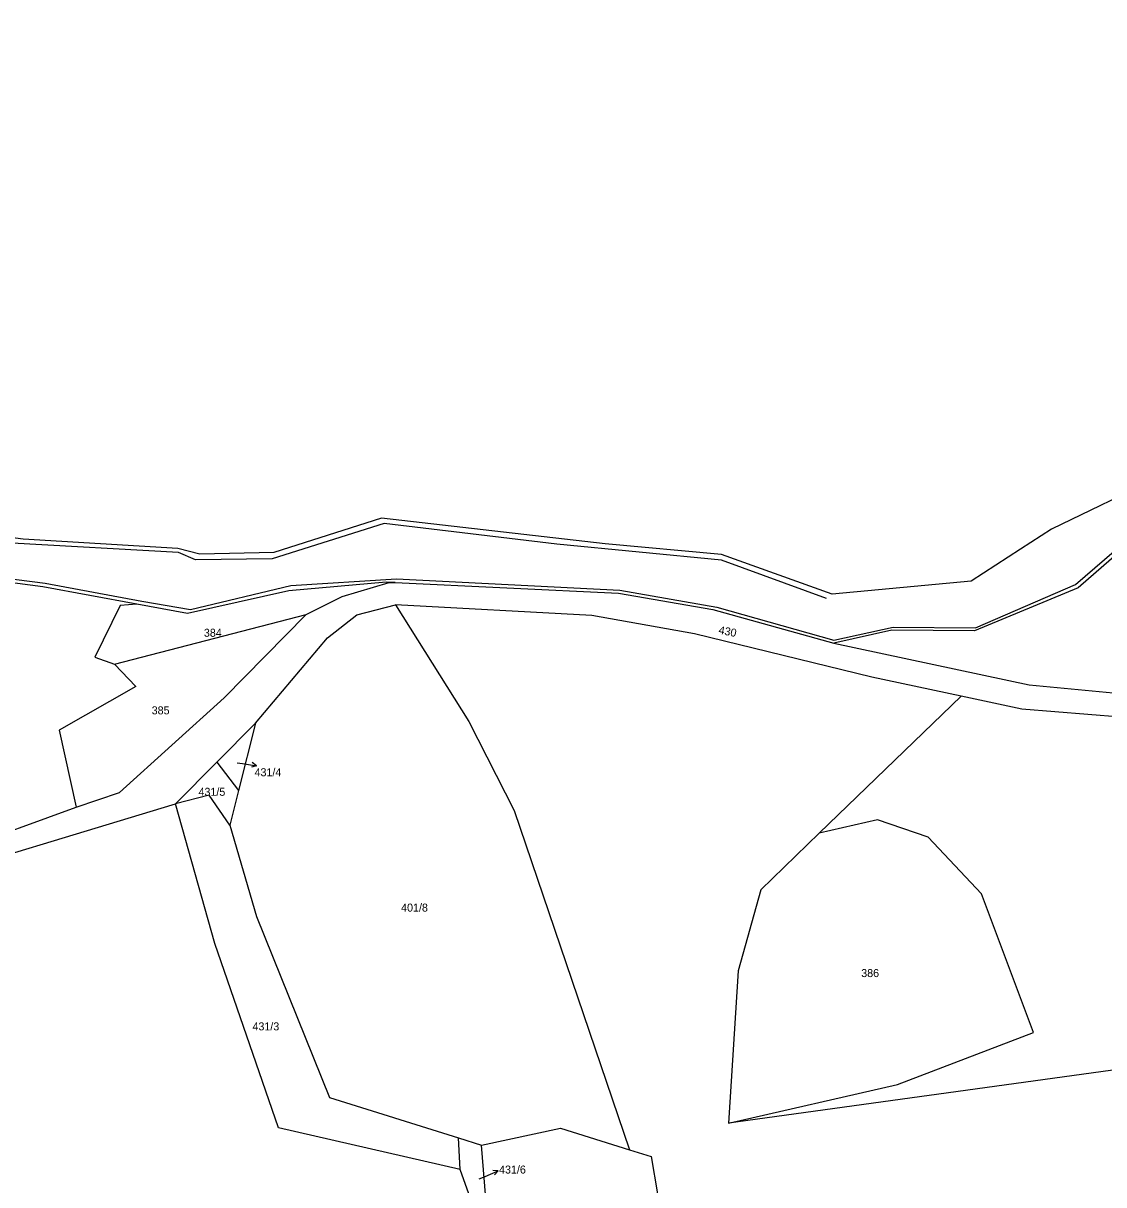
# Model space of a CAD drawing. Extents: x -880531 to -877616, y -1023932 to -1021350.
# Drawn here: x -879514.7 to -879285.2, y -1022591 to -1022344.3 of the extents above; entities that cross this region are included whole.
import ezdxf

# ---------------------------------------------------------------- set-up
doc = ezdxf.new("R2010")
doc.units = 0
for name, color, linetype in [('Hranice parcel', 7, 'Continuous'), ('Parcelní čísla', 7, 'Continuous'), ('Pop  PČ popisy', 7, 'Continuous'), ('Vnitřní kresba', 7, 'Continuous')]:
    doc.layers.add(name, color=color, linetype=linetype)

msp = doc.modelspace()

# ---------------------------------------------------------------- linework, layer by layer
at = {"layer": 'Hranice parcel'}
for p, q in [((-879514.65, -1022453.82), (-879554.59, -1022448.77)), ((-879296.28, -1022451.71), (-879302.87, -1022455.98)), ((-879481.82, -1022455.8), (-879514.65, -1022453.82)), ((-879477.14, -1022457.02), (-879481.82, -1022455.8)), ((-879435.61, -1022467.78), (-879420.02, -1022492.57)), ((-879495.3, -1022480.39), (-879454.54, -1022469.83)), ((-879345.58, -1022516.31), (-879315.42, -1022487.17)), ((-879473.56, -1022501.22), (-879465.35, -1022492.92)), ((-879465.35, -1022492.92), (-879468.94, -1022507.19)), ((-879420.02, -1022492.57), (-879410.4, -1022511.47)), ((-879482.3, -1022510.07), (-879473.56, -1022501.22)), ((-879473.56, -1022501.22), (-879468.94, -1022507.19)), ((-879468.94, -1022507.19), (-879470.81, -1022514.6)), ((-879410.4, -1022511.47), (-879385.9, -1022583.53)), ((-879217.35, -1022557.49), (-879364.9, -1022577.89)), ((-879422.2, -1022581), (-879417.36, -1022582.52)), ((-879421.85, -1022587.72), (-879422.2, -1022581)), ((-879415.4, -1022606.17), (-879417.36, -1022582.52)), ((-879419.69, -1022593.89), (-879421.85, -1022587.72))]:
    msp.add_line(p, q, dxfattribs=at)
for points in [[(-879264.75, -1022429.21), (-879273.42, -1022440.64), (-879296.28, -1022451.71)], [(-879302.87, -1022455.98), (-879313.33, -1022462.75), (-879342.88, -1022465.55), (-879366.37, -1022457.08), (-879391.08, -1022454.8), (-879438.6, -1022449.35), (-879461.44, -1022456.65), (-879477.14, -1022457.02)], [(-879265.79, -1022449.37), (-879273.18, -1022449.04), (-879290.63, -1022464.2), (-879312.6, -1022473.29), (-879330.15, -1022473.16), (-879342.53, -1022475.91)], [(-879490.51, -1022467.67), (-879510.53, -1022463.99), (-879533.14, -1022460.99)], [(-879435.67, -1022463.03), (-879437.61, -1022462.94), (-879458.24, -1022464.82), (-879479.75, -1022469.64), (-879490.51, -1022467.67)], [(-879454.54, -1022469.83), (-879446.95, -1022466.02), (-879436.97, -1022463.05), (-879435.67, -1022463.03)], [(-879435.67, -1022463.03), (-879388.26, -1022465.34), (-879368.23, -1022468.76), (-879342.53, -1022475.91)], [(-879490.51, -1022467.67), (-879494.04, -1022467.9), (-879499.48, -1022478.9), (-879495.3, -1022480.39)], [(-879465.35, -1022492.92), (-879450.06, -1022474.83), (-879443.78, -1022469.92), (-879435.61, -1022467.78)], [(-879315.42, -1022487.17), (-879334.41, -1022483.12), (-879372.08, -1022473.95), (-879393.87, -1022470.04), (-879435.61, -1022467.78)], [(-879503.43, -1022510.75), (-879494.19, -1022507.62), (-879471.96, -1022487.56), (-879454.54, -1022469.83)], [(-879342.53, -1022475.91), (-879301.02, -1022484.77), (-879266.84, -1022488.04), (-879240.35, -1022492.73)], [(-879495.3, -1022480.39), (-879490.77, -1022485.14), (-879507.01, -1022494.4), (-879503.43, -1022510.75)], [(-879205.21, -1022509.09), (-879219.34, -1022505.17), (-879242.06, -1022497.17), (-879267.55, -1022492.75), (-879302.54, -1022489.92), (-879315.42, -1022487.17)], [(-879470.81, -1022514.6), (-879475.15, -1022508.24), (-879482.3, -1022510.07)], [(-879563.05, -1022539.12), (-879554.81, -1022535.76), (-879547.63, -1022531.21), (-879542.21, -1022528.17), (-879482.3, -1022510.07)], [(-879543.35, -1022517.62), (-879533.58, -1022519.17), (-879528.32, -1022519.79), (-879503.43, -1022510.75)], [(-879421.85, -1022587.72), (-879460.46, -1022578.88), (-879473.96, -1022539.75), (-879482.3, -1022510.07)], [(-879364.9, -1022577.89), (-879329.01, -1022569.67), (-879300.09, -1022558.59), (-879311.13, -1022529.2), (-879322.46, -1022517.11), (-879333.2, -1022513.42), (-879345.58, -1022516.31)], [(-879470.81, -1022514.6), (-879465.09, -1022533.95), (-879449.62, -1022572.4), (-879422.2, -1022581)], [(-879345.58, -1022516.31), (-879358.01, -1022528.29), (-879362.82, -1022545.49), (-879364.9, -1022577.89)], [(-879417.36, -1022582.52), (-879400.58, -1022578.91), (-879385.9, -1022583.53)], [(-879385.9, -1022583.53), (-879381.31, -1022584.98), (-879379.94, -1022592.88), (-879404.84, -1022611.84), (-879412.96, -1022613.16), (-879415.4, -1022606.17)]]:
    msp.add_lwpolyline(points, dxfattribs=at)
at = {"layer": 'Pop  PČ popisy'}
for p, q in [((-879469.24, -1022501.32), (-879468.09, -1022501.49)), ((-879465.126, -1022501.959), (-879466.037, -1022501.308)), ((-879468.09, -1022501.49), (-879465.126, -1022501.959)), ((-879465.126, -1022501.959), (-879466.193, -1022502.297)), ((-879417.82, -1022589.73), (-879416.57, -1022589.2)), ((-879416.57, -1022589.2), (-879413.808, -1022588.027)), ((-879413.808, -1022588.027), (-879414.925, -1022587.958)), ((-879413.808, -1022588.027), (-879414.534, -1022588.88))]:
    msp.add_line(p, q, dxfattribs=at)
at = {"layer": 'Vnitřní kresba'}
for p, q in [((-879366.33, -1022458.33), (-879401.32, -1022454.88)), ((-879344.03, -1022466.47), (-879366.33, -1022458.33)), ((-879312.43, -1022472.65), (-879291.15, -1022463.47))]:
    msp.add_line(p, q, dxfattribs=at)
for points in [[(-879291.15, -1022463.47), (-879273.18, -1022447.99), (-879266.28, -1022448.5), (-879260.22, -1022440.08), (-879257.19, -1022435.7), (-879249.62, -1022421.23), (-879238.69, -1022414.32), (-879234.74, -1022393.41), (-879217.41, -1022363.03), (-879196.74, -1022344.26), (-879174.95, -1022345.85), (-879160.96, -1022349.83)], [(-879401.32, -1022454.88), (-879438, -1022450.49), (-879461.76, -1022458.04)], [(-879634.44, -1022479.57), (-879622.04, -1022467.8), (-879605.03, -1022461.6), (-879591.35, -1022456.19), (-879580.07, -1022453.96), (-879555.42, -1022456.98), (-879532.25, -1022460.34), (-879509.99, -1022463.2), (-879489.48, -1022467.02)], [(-879461.76, -1022458.04), (-879478.09, -1022458.2), (-879481.7, -1022456.64), (-879517.02, -1022454.68)], [(-879489.48, -1022467.02), (-879479.15, -1022468.77), (-879457.84, -1022463.68), (-879435.37, -1022462.26)], [(-879435.37, -1022462.26), (-879387.96, -1022464.66), (-879367.35, -1022468.28)], [(-879367.35, -1022468.28), (-879342.47, -1022475.26), (-879329.93, -1022472.56), (-879312.43, -1022472.65)]]:
    msp.add_lwpolyline(points, dxfattribs=at)

# ---------------------------------------------------------------- texts
at = {"layer": 'Parcelní čísla'}
for s, p in [('384', (-879476.29, -1022474.57)), ('385', (-879487.38, -1022491.05)), ('431/4', (-879465.53, -1022504.194)), ('431/5', (-879477.432, -1022508.35)), ('401/8', (-879434.404, -1022532.94)), ('386', (-879336.68, -1022546.85)), ('431/3', (-879465.975, -1022558.17)), ('431/6', (-879413.6, -1022588.58))]:
    msp.add_text(s, height=1.7, dxfattribs=at).set_placement(p)
msp.add_text('430', height=1.7, rotation=349, dxfattribs=at).set_placement((-879367.072, -1022473.904))

doc.saveas('drawing.dxf')
